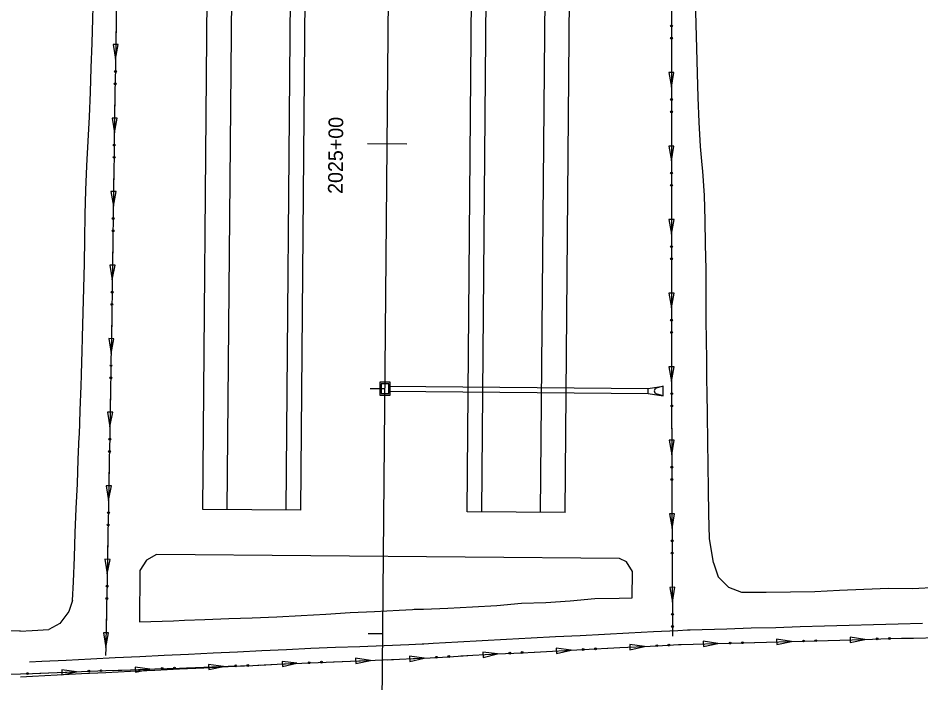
# Model space of a CAD drawing. Extents: x 1611108 to 1749517, y 619561 to 797725.
# Drawn here: x 1713432.3 to 1713801.3, y 759301.7 to 759573.2 of the extents above; entities that cross this region are included whole.
import ezdxf

# ---------------------------------------------------------------- set-up
doc = ezdxf.new("R2010")
doc.units = 0
for name, color, linetype in [('R_Ditch', 7, 'Continuous'), ('R_Drainage', 7, 'Continuous'), ('R_Horz Alg', 7, 'Continuous'), ('R_Horz Alg Stationing', 7, 'Continuous'), ('R_Proposed Const Limits', 7, 'Continuous'), ('R_Proposed Road', 7, 'Continuous'), ('S_EDGE_PAVEMENT', 7, 'Continuous')]:
    doc.layers.add(name, color=color, linetype=linetype)

msp = doc.modelspace()

# ---------------------------------------------------------------- linework, layer by layer
at = {"layer": 'R_Ditch'}
for p, q in [((1713473.3, 759562.38), (1713471.18, 759562.41)), ((1713471.18, 759562.41), (1713472.15, 759556.39)), ((1713472.15, 759556.39), (1713473.3, 759562.38)), ((1713700.35, 759550.96), (1713698.23, 759550.96)), ((1713698.23, 759550.96), (1713699.29, 759544.96)), ((1713699.29, 759544.96), (1713700.35, 759550.96)), ((1713472.86, 759532.34), (1713470.74, 759532.37)), ((1713470.74, 759532.37), (1713471.71, 759526.36)), ((1713471.71, 759526.36), (1713472.86, 759532.34)), ((1713700.35, 759520.92), (1713698.24, 759520.92)), ((1713698.24, 759520.92), (1713699.3, 759514.92)), ((1713699.3, 759514.92), (1713700.35, 759520.92)), ((1713472.41, 759502.31), (1713470.3, 759502.34)), ((1713470.3, 759502.34), (1713471.27, 759496.32)), ((1713471.27, 759496.32), (1713472.41, 759502.31)), ((1713700.36, 759490.88), (1713698.25, 759490.88)), ((1713698.25, 759490.88), (1713699.31, 759484.88)), ((1713699.31, 759484.88), (1713700.36, 759490.88)), ((1713471.97, 759472.27), (1713469.86, 759472.3)), ((1713469.86, 759472.3), (1713470.82, 759466.29)), ((1713470.82, 759466.29), (1713471.97, 759472.27)), ((1713700.37, 759460.84), (1713698.26, 759460.84)), ((1713698.26, 759460.84), (1713699.32, 759454.84)), ((1713699.32, 759454.84), (1713700.37, 759460.84)), ((1713471.51, 759442.24), (1713469.4, 759442.27)), ((1713469.4, 759442.27), (1713470.36, 759436.26)), ((1713470.36, 759436.26), (1713471.51, 759442.24)), ((1713700.41, 759430.81), (1713698.29, 759430.8)), ((1713698.29, 759430.8), (1713699.36, 759424.8)), ((1713699.36, 759424.8), (1713700.41, 759430.81)), ((1713471.02, 759412.2), (1713468.9, 759412.24)), ((1713468.9, 759412.24), (1713469.86, 759406.22)), ((1713469.86, 759406.22), (1713471.02, 759412.2)), ((1713700.48, 759400.77), (1713698.36, 759400.76)), ((1713698.36, 759400.76), (1713699.44, 759394.77)), ((1713699.44, 759394.77), (1713700.48, 759400.77)), ((1713470.5, 759382.17), (1713468.38, 759382.21)), ((1713468.38, 759382.21), (1713469.33, 759376.19)), ((1713469.33, 759376.19), (1713470.5, 759382.17)), ((1713700.58, 759370.73), (1713698.46, 759370.72)), ((1713698.46, 759370.72), (1713699.54, 759364.73)), ((1713699.54, 759364.73), (1713700.58, 759370.73)), ((1713469.94, 759352.13), (1713467.82, 759352.17)), ((1713467.82, 759352.17), (1713468.77, 759346.16)), ((1713468.77, 759346.16), (1713469.94, 759352.13)), ((1713700.71, 759340.7), (1713698.59, 759340.68)), ((1713698.59, 759340.68), (1713699.68, 759334.69)), ((1713699.68, 759334.69), (1713700.71, 759340.7)), ((1713469.35, 759322.1), (1713467.24, 759322.14)), ((1713467.24, 759322.14), (1713468.17, 759316.12)), ((1713468.17, 759316.12), (1713469.35, 759322.1)), ((1713718.3, 759317.78), (1713712.28, 759318.67)), ((1713712.28, 759318.67), (1713712.34, 759316.55)), ((1713712.34, 759316.55), (1713718.3, 759317.78)), ((1713748.33, 759318.6), (1713742.3, 759319.5)), ((1713742.3, 759319.5), (1713742.36, 759317.38)), ((1713742.36, 759317.38), (1713748.33, 759318.6)), ((1713778.36, 759319.46), (1713772.33, 759320.34)), ((1713772.33, 759320.34), (1713772.39, 759318.23)), ((1713772.39, 759318.23), (1713778.36, 759319.46)), ((1713628.3, 759313.49), (1713622.25, 759314.21)), ((1713622.25, 759314.21), (1713622.36, 759312.1)), ((1713658.29, 759315.04), (1713652.25, 759315.79)), ((1713652.25, 759315.79), (1713652.36, 759313.68)), ((1713652.36, 759313.68), (1713658.29, 759315.04)), ((1713688.29, 759316.58), (1713682.25, 759317.33)), ((1713682.25, 759317.33), (1713682.35, 759315.22)), ((1713682.35, 759315.22), (1713688.29, 759316.58)), ((1713546.27, 759309.67), (1713540.22, 759310.44)), ((1713540.22, 759310.44), (1713540.33, 759308.33)), ((1713576.28, 759310.88), (1713570.24, 759311.7)), ((1713570.24, 759311.7), (1713570.33, 759309.58)), ((1713570.33, 759309.58), (1713576.28, 759310.88)), ((1713598.3, 759311.83), (1713592.25, 759312.55)), ((1713592.25, 759312.55), (1713592.37, 759310.44)), ((1713592.37, 759310.44), (1713598.3, 759311.83)), ((1713622.36, 759312.1), (1713628.3, 759313.49)), ((1713456.22, 759306.2), (1713450.19, 759307.03)), ((1713450.19, 759307.03), (1713450.27, 759304.92)), ((1713486.24, 759307.32), (1713480.2, 759308.16)), ((1713480.2, 759308.16), (1713480.28, 759306.05)), ((1713480.28, 759306.05), (1713486.24, 759307.32)), ((1713516.26, 759308.4), (1713510.22, 759309.24)), ((1713510.22, 759309.24), (1713510.3, 759307.13)), ((1713510.3, 759307.13), (1713516.26, 759308.4)), ((1713540.33, 759308.33), (1713546.27, 759309.67)), ((1713450.27, 759304.92), (1713456.22, 759306.2))]:
    msp.add_line(p, q, dxfattribs=at)
for points in [[(1713699.28, 759580.84), (1713699.28, 759570.84), (1713699.29, 759560.84), (1713699.29, 759550.84), (1713699.29, 759540.83), (1713699.29, 759530.83), (1713699.3, 759520.83), (1713699.3, 759513.36), (1713699.3, 759510.83), (1713699.3, 759500.83), (1713699.3, 759490.83), (1713699.31, 759480.83), (1713699.31, 759470.83), (1713699.31, 759460.83), (1713699.32, 759450.83), (1713699.33, 759440.83), (1713699.35, 759430.83), (1713699.36, 759425.22), (1713699.37, 759420.83), (1713699.39, 759410.83), (1713699.42, 759400.83), (1713699.42, 759400.15), (1713699.45, 759390.83), (1713699.48, 759380.83), (1713699.52, 759370.83), (1713699.56, 759360.83), (1713699.6, 759350.83), (1713699.65, 759340.83), (1713699.7, 759330.82), (1713699.76, 759320.93), (1713699.76, 759320.82)], [(1713472.37, 759571.39), (1713472.25, 759562.82), (1713472.15, 759556.39)], [(1713472.37, 759571.43), (1713472.37, 759571.39)], [(1713699.29, 759559.99), (1713699.29, 759559.96)], [(1713699.29, 759559.96), (1713699.29, 759550.84), (1713699.29, 759544.96)], [(1713471.93, 759541.36), (1713471.8, 759532.82), (1713471.71, 759526.36)], [(1713471.93, 759541.4), (1713471.93, 759541.36)], [(1713699.29, 759529.96), (1713699.29, 759529.92)], [(1713699.29, 759529.92), (1713699.3, 759520.83), (1713699.3, 759514.92)], [(1713471.49, 759511.32), (1713471.36, 759502.82), (1713471.27, 759496.32)], [(1713471.49, 759511.36), (1713471.49, 759511.32)], [(1713699.3, 759499.92), (1713699.3, 759499.88)], [(1713699.3, 759499.88), (1713699.3, 759490.83), (1713699.31, 759484.88)], [(1713471.05, 759481.29), (1713470.92, 759472.83), (1713470.82, 759466.29)], [(1713471.05, 759481.33), (1713471.05, 759481.29)], [(1713699.31, 759469.88), (1713699.31, 759469.84)], [(1713699.31, 759469.84), (1713699.31, 759460.83), (1713699.32, 759454.84)], [(1713470.6, 759451.25), (1713470.46, 759442.83), (1713470.36, 759436.26)], [(1713470.6, 759451.29), (1713470.6, 759451.25)], [(1713699.34, 759439.84), (1713699.34, 759439.8)], [(1713699.34, 759439.8), (1713699.35, 759430.83), (1713699.36, 759425.22), (1713699.36, 759424.8)], [(1713470.11, 759421.22), (1713469.97, 759412.83), (1713469.86, 759406.22)], [(1713470.11, 759421.26), (1713470.11, 759421.22)], [(1713699.39, 759409.8), (1713699.39, 759409.77)], [(1713699.39, 759409.77), (1713699.42, 759400.83), (1713699.42, 759400.15), (1713699.44, 759394.77)], [(1713469.6, 759391.19), (1713469.45, 759382.83), (1713469.33, 759376.19)], [(1713469.6, 759391.22), (1713469.6, 759391.19)], [(1713699.48, 759379.77), (1713699.49, 759379.73)], [(1713699.49, 759379.73), (1713699.52, 759370.83), (1713699.54, 759364.73)], [(1713469.05, 759361.15), (1713468.9, 759352.84), (1713468.77, 759346.16)], [(1713469.05, 759361.19), (1713469.05, 759361.15)], [(1713699.61, 759349.73), (1713699.61, 759349.69)], [(1713699.61, 759349.69), (1713699.65, 759340.83), (1713699.68, 759334.69)], [(1713468.47, 759331.12), (1713468.31, 759322.95), (1713468.31, 759322.84), (1713468.3, 759322.24), (1713468.29, 759322.02), (1713468.26, 759320.68), (1713468.24, 759319.59), (1713468.18, 759316.45), (1713468.17, 759316.12)], [(1713468.47, 759331.16), (1713468.47, 759331.12)], [(1713437.05, 759310.24), (1713442.04, 759310.49), (1713452.04, 759311), (1713462.03, 759311.5), (1713472.03, 759312), (1713482.03, 759312.47), (1713492.02, 759312.95), (1713502.02, 759313.42), (1713512.01, 759313.9), (1713522.01, 759314.37), (1713532, 759314.85), (1713542, 759315.32), (1713552, 759315.8), (1713561.99, 759316.2), (1713571.99, 759316.59), (1713581.98, 759316.99), (1713591.98, 759317.39), (1713597.48, 759317.61), (1713598.19, 759317.65), (1713601.98, 759317.86), (1713611.97, 759318.42), (1713621.97, 759318.97), (1713631.96, 759319.52), (1713641.96, 759320.05), (1713651.95, 759320.56), (1713661.95, 759321.07), (1713671.94, 759321.59), (1713681.94, 759322.1), (1713691.93, 759322.61), (1713701.93, 759323.13), (1713705.93, 759323.33), (1713706.93, 759323.38), (1713711.92, 759323.54), (1713721.92, 759323.81), (1713731.92, 759324.09), (1713741.92, 759324.36), (1713751.91, 759324.64), (1713761.91, 759324.91), (1713771.91, 759325.2), (1713781.91, 759325.49), (1713791.9, 759325.78), (1713801.9, 759326.04)], [(1713433.29, 759304.21), (1713438.29, 759304.46), (1713448.28, 759304.96), (1713458.28, 759305.46), (1713468.27, 759305.96), (1713478.27, 759306.43), (1713488.27, 759306.91), (1713498.26, 759307.38), (1713508.26, 759307.86), (1713518.25, 759308.33), (1713528.25, 759308.81), (1713538.24, 759309.28), (1713548.24, 759309.76), (1713558.24, 759310.16), (1713568.23, 759310.55), (1713578.23, 759310.95), (1713588.23, 759311.35), (1713593.72, 759311.58), (1713594.43, 759311.62), (1713598.22, 759311.82), (1713608.22, 759312.38), (1713618.21, 759312.93), (1713628.21, 759313.49), (1713638.2, 759314.01), (1713648.2, 759314.52), (1713658.19, 759315.03), (1713668.19, 759315.55), (1713678.18, 759316.06), (1713688.18, 759316.57), (1713698.17, 759317.09), (1713702.17, 759317.29), (1713703.17, 759317.34), (1713708.17, 759317.5), (1713718.17, 759317.77), (1713728.16, 759318.05), (1713738.16, 759318.32), (1713748.16, 759318.6), (1713758.16, 759318.87), (1713768.15, 759319.16), (1713778.15, 759319.45), (1713788.15, 759319.75), (1713798.15, 759320), (1713808.15, 759320.23)], [(1713703.31, 759317.35), (1713708.17, 759317.5), (1713718.17, 759317.77), (1713718.3, 759317.78)], [(1713733.3, 759318.19), (1713733.34, 759318.19)], [(1713733.34, 759318.19), (1713738.16, 759318.32), (1713748.16, 759318.6), (1713748.33, 759318.6)], [(1713763.32, 759319.02), (1713763.36, 759319.03)], [(1713763.36, 759319.03), (1713768.15, 759319.16), (1713778.15, 759319.45), (1713778.36, 759319.46)], [(1713793.35, 759319.88), (1713793.39, 759319.88)], [(1713793.39, 759319.88), (1713798.15, 759320), (1713808.15, 759320.23), (1713808.38, 759320.24)], [(1713643.28, 759314.27), (1713643.31, 759314.27)], [(1713643.31, 759314.27), (1713648.2, 759314.52), (1713658.19, 759315.03), (1713658.29, 759315.04)], [(1713673.27, 759315.81), (1713673.31, 759315.81)], [(1713673.31, 759315.81), (1713678.18, 759316.06), (1713688.18, 759316.57), (1713688.29, 759316.58)], [(1713703.27, 759317.35), (1713703.31, 759317.35)], [(1713170.9, 759304.21), (1713433.28, 759305.32), (1713438.28, 759305.51), (1713448.27, 759305.9), (1713458.27, 759306.28), (1713468.27, 759306.67), (1713478.26, 759307.03), (1713488.26, 759307.39), (1713498.26, 759307.75), (1713508.25, 759308.11), (1713518.25, 759308.48), (1713528.25, 759308.84), (1713530.25, 759308.91), (1713538.24, 759309.29), (1713548.24, 759309.76), (1713558.24, 759310.16), (1713568.23, 759310.56), (1713578.23, 759310.96), (1713581.13, 759311.07)], [(1713561.26, 759310.28), (1713561.29, 759310.28)], [(1713561.29, 759310.28), (1713568.23, 759310.56), (1713576.28, 759310.88)], [(1713583.32, 759311.15), (1713588.23, 759311.35), (1713593.72, 759311.58), (1713594.43, 759311.62), (1713598.22, 759311.82), (1713598.3, 759311.83)], [(1713613.28, 759312.66), (1713613.32, 759312.66)], [(1713613.32, 759312.66), (1713618.21, 759312.93), (1713628.21, 759313.49), (1713628.3, 759313.49)], [(1713471.21, 759306.78), (1713471.25, 759306.78)], [(1713471.25, 759306.78), (1713478.26, 759307.03), (1713486.24, 759307.32)], [(1713501.23, 759307.86), (1713501.27, 759307.86)], [(1713501.27, 759307.86), (1713508.25, 759308.11), (1713516.26, 759308.4)], [(1713531.25, 759308.96), (1713531.28, 759308.96)], [(1713531.29, 759308.96), (1713538.24, 759309.29), (1713546.27, 759309.67)], [(1713441.2, 759305.62), (1713441.23, 759305.62)], [(1713441.23, 759305.62), (1713448.27, 759305.9), (1713456.22, 759306.2)]]:
    msp.add_lwpolyline(points, dxfattribs=at)
for centre in [(1713699.32, 759569.99), (1713699.32, 759564.98), (1713472.12, 759551.39), (1713472.04, 759546.38), (1713699.33, 759539.95), (1713699.33, 759534.94), (1713471.67, 759521.35), (1713471.6, 759516.34), (1713699.34, 759509.91), (1713699.34, 759504.9), (1713471.23, 759491.32), (1713471.16, 759486.31), (1713699.34, 759479.87), (1713699.35, 759474.86), (1713470.79, 759461.28), (1713470.71, 759456.27), (1713699.36, 759449.84), (1713699.37, 759444.83), (1713470.31, 759431.25), (1713470.23, 759426.24), (1713699.41, 759419.8), (1713699.42, 759414.79), (1713469.81, 759401.22), (1713469.72, 759396.21), (1713699.49, 759389.76), (1713699.5, 759384.75), (1713469.27, 759371.18), (1713469.18, 759366.17), (1713699.6, 759359.72), (1713699.62, 759354.71), (1713468.71, 759341.15), (1713468.61, 759336.14), (1713699.74, 759329.68), (1713699.77, 759324.67), (1713723.31, 759317.95), (1713728.32, 759318.09), (1713753.33, 759318.78), (1713758.34, 759318.92), (1713783.36, 759319.64), (1713788.37, 759319.79), (1713633.29, 759313.79), (1713638.3, 759314.05), (1713663.29, 759315.33), (1713668.29, 759315.59), (1713693.29, 759316.87), (1713698.29, 759317.13), (1713551.27, 759309.92), (1713556.27, 759310.12), (1713603.3, 759312.14), (1713608.3, 759312.42), (1713461.22, 759306.43), (1713466.23, 759306.63), (1713491.24, 759307.54), (1713496.25, 759307.72), (1713521.26, 759308.62), (1713526.27, 759308.8), (1713436.21, 759305.47)]:
    msp.add_circle(centre, 0.375, dxfattribs=at)
at = {"layer": 'R_Drainage'}
for p, q in [((1713583.77, 759422.84), (1713689.78, 759421.91)), ((1713689.76, 759419.91), (1713689.78, 759421.91)), ((1713689.78, 759421.91), (1713695.91, 759422.86)), ((1713695.91, 759422.86), (1713693.1, 759421.99)), ((1713695.88, 759418.86), (1713695.91, 759422.86)), ((1713583.77, 759420.84), (1713689.76, 759419.91)), ((1713689.76, 759419.91), (1713695.88, 759418.86)), ((1713695.88, 759418.86), (1713693.08, 759419.77))]:
    msp.add_line(p, q, dxfattribs=at)
for points in [[(1713580.1, 759419.19), (1713584.44, 759419.19), (1713584.44, 759424.52), (1713580.1, 759424.52)], [(1713580.77, 759419.85), (1713583.77, 759419.85), (1713583.77, 759423.85), (1713580.77, 759423.85)]]:
    msp.add_lwpolyline(points, close=True, dxfattribs=at)
msp.add_arc((1713693.44, 759420.88), 1.17, 107.0299, 251.9701, dxfattribs=at)
at = {"layer": 'R_Horz Alg'}
msp.add_line((1713561.33, 757021.94), (1713607.03, 762259.43), dxfattribs=at)
at = {"layer": 'R_Horz Alg Stationing'}
for points in [[(1713575.14, 759521.92), (1713591.14, 759521.78)], [(1713576.27, 759421.9), (1713582.27, 759421.85)], [(1713575.4, 759321.91), (1713581.4, 759321.86)]]:
    msp.add_lwpolyline(points, dxfattribs=at)
at = {"layer": 'R_Proposed Const Limits'}
msp.add_line((1713433.1, 759322.82), (1713433.1, 759322.82), dxfattribs=at)
for points in [[(1713454.64, 759335.37), (1713454.97, 759342.96), (1713455.39, 759352.96), (1713455.74, 759362.95), (1713456.13, 759372.95), (1713456.57, 759382.95), (1713456.89, 759392.95), (1713457.37, 759402.26), (1713457.39, 759402.94), (1713457.73, 759412.94), (1713458.07, 759422.94), (1713458.22, 759427.32), (1713458.4, 759432.93), (1713458.53, 759436.92), (1713458.7, 759442.93), (1713458.98, 759452.93), (1713459.26, 759462.93), (1713459.43, 759472.93), (1713459.6, 759482.93), (1713459.78, 759492.92), (1713460.03, 759502.92), (1713460.45, 759512.92), (1713460.59, 759515.44), (1713461.01, 759522.91), (1713461.57, 759532.91), (1713461.96, 759542.91), (1713462.27, 759552.9), (1713462.57, 759562.9), (1713462.88, 759572.9), (1713463.19, 759582.9)], [(1713716.45, 759350.68), (1713714.86, 759360.69), (1713714.63, 759370.7), (1713714.46, 759380.7), (1713714.3, 759390.7), (1713714.15, 759400.02), (1713714.14, 759400.7), (1713713.98, 759410.7), (1713713.86, 759420.7), (1713713.81, 759425.09), (1713713.75, 759430.7), (1713713.71, 759434.7), (1713713.64, 759440.71), (1713713.53, 759450.71), (1713713.47, 759460.71), (1713713.44, 759470.71), (1713713.25, 759480.71), (1713713.05, 759490.71), (1713712.85, 759500.71), (1713712.09, 759510.72), (1713711.85, 759513.25), (1713711.19, 759520.73), (1713710.57, 759530.74), (1713710.19, 759540.74), (1713709.95, 759550.74), (1713709.71, 759560.74), (1713709.43, 759570.75), (1713709.11, 759580.75)], [(1713488.92, 759354.06), (1713484.79, 759351.82), (1713482.12, 759347.52), (1713481.93, 759326.61)], [(1713678.07, 759352.41), (1713488.92, 759354.06)], [(1713683.28, 759336.45), (1713683.37, 759347.11), (1713680.92, 759351.06), (1713678.07, 759352.41)], [(1713716.45, 759350.68), (1713718.39, 759344.98), (1713722.56, 759340.81), (1713727.95, 759338.71)], [(1713727.95, 759338.71), (1713737.95, 759338.76), (1713747.95, 759338.82), (1713757.95, 759339.04), (1713767.94, 759339.52), (1713777.94, 759340.01), (1713787.94, 759340.35), (1713797.94, 759340.24), (1713807.93, 759340.7), (1713817.93, 759341.29), (1713827.92, 759341.87), (1713837.92, 759342.08), (1713847.92, 759342.14), (1713857.92, 759342.18), (1713867.92, 759342.23), (1713877.92, 759342.42), (1713887.92, 759342.24), (1713897.92, 759342.45), (1713907.92, 759342.72), (1713917.92, 759343.04), (1713927.91, 759343.3), (1713927.91, 759343.3)], [(1713433.3, 759322.83), (1713203.69, 759327.08), (1713189.85, 759329.4), (1713174.98, 759336.98)], [(1713481.93, 759326.61), (1713495.79, 759327.01), (1713500.34, 759327.24), (1713508.67, 759327.52), (1713518.41, 759327.91), (1713528.05, 759328.19), (1713538.04, 759328.71), (1713548.04, 759329.13), (1713558.03, 759329.78), (1713568.03, 759330.39), (1713578.02, 759330.89), (1713588.02, 759331.34), (1713593.51, 759331.67), (1713594.23, 759331.72), (1713598.01, 759331.84), (1713608.01, 759332.22), (1713618.01, 759332.74), (1713628, 759333.26), (1713637.99, 759334.17), (1713647.99, 759334.45), (1713657.98, 759335.12), (1713667.97, 759336.09), (1713677.97, 759336.25), (1713683.28, 759336.45)], [(1713454.64, 759335.37), (1713453.04, 759330.88), (1713449.41, 759325.94), (1713444.91, 759323.42)], [(1713433.1, 759322.82), (1713438.1, 759323.08), (1713444.91, 759323.42)]]:
    msp.add_lwpolyline(points, dxfattribs=at)
at = {"layer": 'R_Proposed Road'}
for p, q in [((1713541.83, 759372.2), (1713567.03, 762259.78)), ((1713547.83, 759372.15), (1713573.03, 762259.72)), ((1713615.83, 759371.56), (1713641.03, 762259.13)), ((1713621.83, 759371.5), (1713647.03, 762259.08)), ((1713645.83, 759371.3), (1713657.58, 760717.92)), ((1713655.83, 759371.21), (1713666.54, 760598.16)), ((1713507.84, 759372.5), (1713517.89, 760524.26)), ((1713517.83, 759372.41), (1713527.89, 760524.17)), ((1713547.83, 759372.15), (1713507.84, 759372.5)), ((1713655.83, 759371.21), (1713615.83, 759371.56))]:
    msp.add_line(p, q, dxfattribs=at)
at = {"layer": 'S_EDGE_PAVEMENT'}
msp.add_lwpolyline([(1713472.54, 759582.82), (1713472.39, 759572.82), (1713472.25, 759562.82), (1713472.1, 759552.82), (1713471.95, 759542.82), (1713471.8, 759532.82), (1713471.66, 759522.82), (1713471.55, 759515.35), (1713471.51, 759512.82), (1713471.36, 759502.82), (1713471.22, 759492.82), (1713471.07, 759482.83), (1713470.92, 759472.83), (1713470.77, 759462.83), (1713470.62, 759452.83), (1713470.46, 759442.83), (1713470.3, 759432.83), (1713470.21, 759427.22), (1713470.14, 759422.83), (1713469.97, 759412.83), (1713469.8, 759402.83), (1713469.79, 759402.15), (1713469.63, 759392.83), (1713469.45, 759382.83), (1713469.27, 759372.84), (1713469.08, 759362.84), (1713468.9, 759352.84), (1713468.7, 759342.84), (1713468.51, 759332.84), (1713468.31, 759322.95), (1713468.31, 759322.84), (1713468.3, 759322.24), (1713468.29, 759322.02), (1713468.26, 759320.68), (1713468.24, 759319.59), (1713468.18, 759316.45), (1713468.17, 759315.98), (1713468.1, 759312.84)], dxfattribs=at)

# ---------------------------------------------------------------- texts
at = {"layer": 'R_Horz Alg Stationing'}
msp.add_text('2025+00', height=6, rotation=89.5, dxfattribs=at).set_placement((1713564.96, 759501.36))

doc.saveas('drawing.dxf')
